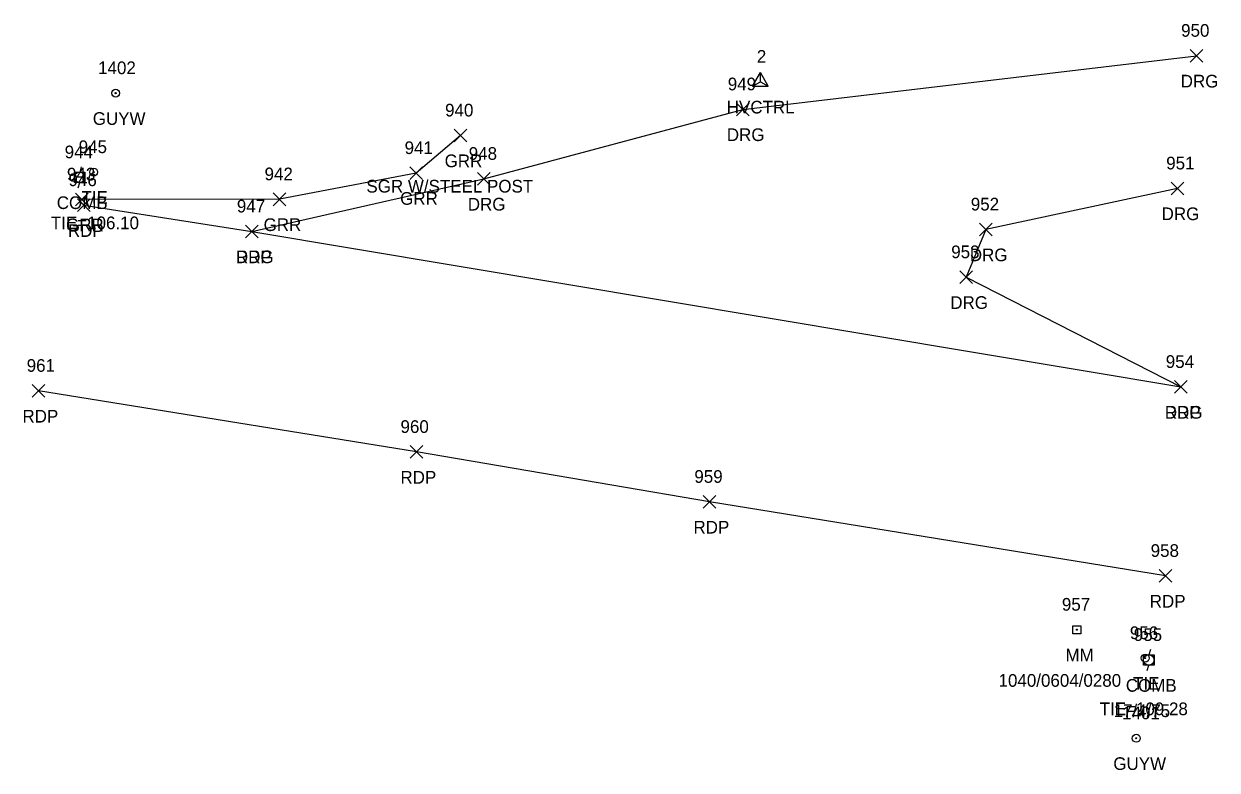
# Model space of a CAD drawing. Extents: x 1514253 to 1516033, y 782541 to 785002.
# Drawn here: x 1515845 to 1516033.2, y 782540.9 to 782658.6 of the extents above; entities that cross this region are included whole.
import ezdxf

# ---------------------------------------------------------------- set-up
doc = ezdxf.new("R2010")
doc.units = 0
for name, color, linetype in [('C_A', 7, 'Continuous'), ('C_C', 7, 'Continuous'), ('C_I', 7, 'Continuous'), ('CBP', 7, 'Continuous'), ('CPSM', 7, 'Continuous'), ('P_A', 7, 'Continuous'), ('P_I', 7, 'Continuous'), ('P_TIC', 7, 'Continuous'), ('PET', 7, 'Continuous'), ('R_A', 7, 'Continuous'), ('R_C', 7, 'Continuous'), ('R_I', 7, 'Continuous'), ('R_TIC', 7, 'Continuous'), ('RDG', 7, 'Continuous'), ('RGR', 7, 'Continuous'), ('S_A', 7, 'Continuous'), ('S_C', 7, 'Continuous'), ('S_I', 7, 'Continuous'), ('SRM', 7, 'Continuous'), ('U_A', 7, 'Continuous'), ('U_C', 7, 'Continuous'), ('U_I', 7, 'Continuous'), ('UP', 7, 'Continuous'), ('UPGW', 7, 'Continuous')]:
    doc.layers.add(name, color=color, linetype=linetype)

msp = doc.modelspace()

# ---------------------------------------------------------------- linework, layer by layer
at = {"layer": 'CBP'}
for centre, radius in [((1515856.01, 782635.23), 0.625), ((1515856.01, 782635.23), 0.0833), ((1516021.84, 782558.59), 0.625), ((1516021.84, 782558.59), 0.0833)]:
    msp.add_circle(centre, radius, dxfattribs=at)
at = {"layer": 'CPSM'}
for p, q in [((1515959.9, 782648.76), (1515961.15, 782650.92)), ((1515962.4, 782648.76), (1515961.15, 782650.92)), ((1515961.15, 782649.48), (1515961.15, 782650.92)), ((1515959.9, 782648.76), (1515961.15, 782649.48)), ((1515959.9, 782648.76), (1515962.4, 782648.76)), ((1515961.15, 782649.48), (1515961.15, 782649.48)), ((1515961.15, 782649.48), (1515962.4, 782648.76))]:
    msp.add_line(p, q, dxfattribs=at)
at = {"layer": 'P_TIC'}
for points in [[(1515853.46, 782629.02), (1515855.46, 782631.02)], [(1515855.46, 782629.02), (1515853.46, 782631.02)], [(1515879.96, 782624.87), (1515881.96, 782626.87)], [(1515881.96, 782624.87), (1515879.96, 782626.87)], [(1515846.3, 782599.74), (1515848.3, 782601.74)], [(1515848.3, 782599.74), (1515846.3, 782601.74)], [(1516026.44, 782600.35), (1516028.44, 782602.35)], [(1516028.44, 782600.35), (1516026.44, 782602.35)], [(1515905.9, 782590.1), (1515907.9, 782592.1)], [(1515907.9, 782590.1), (1515905.9, 782592.1)], [(1515952.11, 782582.23), (1515954.11, 782584.23)], [(1515954.11, 782582.23), (1515952.11, 782584.23)], [(1516024.06, 782570.55), (1516026.06, 782572.55)], [(1516026.06, 782570.55), (1516024.06, 782572.55)]]:
    msp.add_lwpolyline(points, dxfattribs=at)
at = {"layer": 'PET'}
for points in [[(1515854.46, 782630.02), (1515880.96, 782625.87), (1516027.44, 782601.35)], [(1516025.06, 782571.55), (1515953.11, 782583.23), (1515906.9, 782591.1), (1515847.3, 782600.74)]]:
    msp.add_lwpolyline(points, dxfattribs=at)
at = {"layer": 'R_TIC'}
for points in [[(1516028.95, 782652.58), (1516030.95, 782654.58)], [(1516030.95, 782652.58), (1516028.95, 782654.58)], [(1515957.38, 782644.13), (1515959.38, 782646.13)], [(1515959.38, 782644.13), (1515957.38, 782646.13)], [(1515912.88, 782640.01), (1515914.88, 782642.01)], [(1515914.88, 782640.01), (1515912.88, 782642.01)], [(1515905.85, 782634.08), (1515907.85, 782636.08)], [(1515907.85, 782634.08), (1515905.85, 782636.08)], [(1515916.52, 782633.17), (1515918.52, 782635.17)], [(1515918.52, 782633.17), (1515916.52, 782635.17)], [(1516025.94, 782631.66), (1516027.94, 782633.66)], [(1516027.94, 782631.66), (1516025.94, 782633.66)], [(1515853.16, 782629.91), (1515855.16, 782631.91)], [(1515855.16, 782629.91), (1515853.16, 782631.91)], [(1515884.33, 782629.94), (1515886.33, 782631.94)], [(1515886.33, 782629.94), (1515884.33, 782631.94)], [(1515879.96, 782624.87), (1515881.96, 782626.87)], [(1515881.96, 782624.87), (1515879.96, 782626.87)], [(1515995.69, 782625.18), (1515997.69, 782627.18)], [(1515997.69, 782625.18), (1515995.69, 782627.18)], [(1515992.61, 782617.66), (1515994.61, 782619.66)], [(1515994.61, 782617.66), (1515992.61, 782619.66)], [(1516026.44, 782600.35), (1516028.44, 782602.35)], [(1516028.44, 782600.35), (1516026.44, 782602.35)]]:
    msp.add_lwpolyline(points, dxfattribs=at)
at = {"layer": 'RDG'}
for points in [[(1515880.96, 782625.87), (1515917.52, 782634.17), (1515958.38, 782645.13), (1516029.95, 782653.58)], [(1516026.94, 782632.66), (1515996.69, 782626.18), (1515993.61, 782618.66), (1516027.44, 782601.35)]]:
    msp.add_lwpolyline(points, dxfattribs=at)
at = {"layer": 'RGR'}
msp.add_lwpolyline([(1515913.88, 782641.01), (1515906.85, 782635.08), (1515885.33, 782630.94), (1515854.16, 782630.91)], dxfattribs=at)
at = {"layer": 'SRM'}
msp.add_lwpolyline([(1516010.44, 782563.69), (1516011.69, 782563.69), (1516011.69, 782562.44), (1516010.44, 782562.44)], close=True, dxfattribs=at)
msp.add_circle((1516011.07, 782563.07), 0.0833, dxfattribs=at)
at = {"layer": 'UP'}
for p, q in [((1515852.97, 782633.58), (1515852.97, 782635.24)), ((1515852.97, 782635.24), (1515854.64, 782635.24)), ((1515854.06, 782636.08), (1515853.81, 782635.24)), ((1515854.64, 782635.24), (1515854.64, 782633.58)), ((1515854.64, 782633.58), (1515852.97, 782633.58)), ((1515853.56, 782632.74), (1515853.81, 782633.58)), ((1515853.81, 782634.41), (1515853.81, 782634.41)), ((1516022.65, 782559.96), (1516022.4, 782559.12)), ((1516021.56, 782557.46), (1516021.56, 782559.12)), ((1516021.56, 782559.12), (1516023.23, 782559.12)), ((1516022.4, 782558.29), (1516022.4, 782558.29)), ((1516023.23, 782559.12), (1516023.23, 782557.46)), ((1516023.23, 782557.46), (1516021.56, 782557.46)), ((1516022.15, 782556.62), (1516022.4, 782557.46))]:
    msp.add_line(p, q, dxfattribs=at)
for centre in [(1515853.81, 782634.41), (1516022.4, 782558.29)]:
    msp.add_circle(centre, 0.833, dxfattribs=at)
at = {"layer": 'UPGW'}
for centre, radius in [((1515859.48, 782647.68), 0.625), ((1515859.48, 782647.68), 0.0833), ((1516020.42, 782545.95), 0.625), ((1516020.42, 782545.95), 0.0833)]:
    msp.add_circle(centre, radius, dxfattribs=at)

# ---------------------------------------------------------------- texts
at = {"layer": 'C_A'}
for s, p in [('HVCTRL', (1515955.85, 782644.48)), ('TIE', (1515854.09, 782630.23)), ('TIE', (1516019.92, 782553.59))]:
    msp.add_text(s, height=2, dxfattribs=at).set_placement(p)
at = {"layer": 'C_C'}
for s, p in [('TIE=106.10', (1515849.26, 782626.23)), ('TIE=109.28', (1516014.66, 782549.59))]:
    msp.add_text(s, height=2, dxfattribs=at).set_placement(p)
at = {"layer": 'C_I'}
for s, p in [('2', (1515960.59, 782652.48)), ('945', (1515853.65, 782638.23)), ('956', (1516019.42, 782561.59))]:
    msp.add_text(s, height=2, dxfattribs=at).set_placement(p)
at = {"layer": 'P_A'}
for p in [(1515851.95, 782625.02), (1515878.44, 782620.87), (1515844.78, 782595.74), (1516024.93, 782596.35), (1515904.39, 782586.1), (1515950.6, 782578.23), (1516022.55, 782566.55)]:
    msp.add_text('RDP', height=2, dxfattribs=at).set_placement(p)
at = {"layer": 'P_I'}
for s, p in [('946', (1515852.04, 782633.02)), ('947', (1515878.59, 782628.87)), ('961', (1515845.45, 782603.74)), ('954', (1516025.08, 782604.35)), ('960', (1515904.4, 782594.1)), ('959', (1515950.74, 782586.23)), ('958', (1516022.7, 782574.55))]:
    msp.add_text(s, height=2, dxfattribs=at).set_placement(p)
at = {"layer": 'R_A'}
for s, p in [('DRG', (1516027.44, 782648.58)), ('DRG', (1515955.86, 782640.13)), ('GRR', (1515911.36, 782636.01)), ('GRR', (1515904.34, 782630.08)), ('DRG', (1515915.01, 782629.17)), ('DRG', (1516024.43, 782627.66)), ('GRR', (1515851.65, 782625.91)), ('GRR', (1515882.81, 782625.94)), ('DRG', (1515878.44, 782620.87)), ('DRG', (1515994.18, 782621.18)), ('DRG', (1515991.1, 782613.66)), ('DRG', (1516024.93, 782596.35))]:
    msp.add_text(s, height=2, dxfattribs=at).set_placement(p)
at = {"layer": 'R_C'}
msp.add_text('SGR W/STEEL POST', height=2, dxfattribs=at).set_placement((1515899.02, 782632.01))
at = {"layer": 'R_I'}
for s, p in [('950', (1516027.5, 782656.58)), ('949', (1515956.01, 782648.13)), ('940', (1515911.43, 782644.01)), ('941', (1515905.05, 782638.08)), ('948', (1515915.16, 782637.17)), ('951', (1516025.15, 782635.66)), ('943', (1515851.8, 782633.91)), ('942', (1515882.96, 782633.94)), ('952', (1515994.33, 782629.18)), ('947', (1515878.59, 782628.87)), ('953', (1515991.25, 782621.66)), ('954', (1516025.08, 782604.35))]:
    msp.add_text(s, height=2, dxfattribs=at).set_placement(p)
at = {"layer": 'S_A'}
msp.add_text('MM', height=2, dxfattribs=at).set_placement((1516009.26, 782558.07))
at = {"layer": 'S_C'}
msp.add_text('1040/0604/0280', height=2, dxfattribs=at).set_placement((1515998.71, 782554.07))
at = {"layer": 'S_I'}
msp.add_text('957', height=2, dxfattribs=at).set_placement((1516008.7, 782566.07))
at = {"layer": 'U_A'}
for s, p in [('GUYW', (1515855.87, 782642.68)), ('COMB', (1515850.19, 782629.41)), ('COMB', (1516018.78, 782553.29)), ('GUYW', (1516016.81, 782540.95))]:
    msp.add_text(s, height=2, dxfattribs=at).set_placement(p)
at = {"layer": 'U_C'}
msp.add_text('17/4/75', height=2, dxfattribs=at).set_placement((1516016.85, 782549.29))
at = {"layer": 'U_I'}
for s, p in [('1402', (1515856.71, 782650.68)), ('944', (1515851.44, 782637.41)), ('955', (1516020.04, 782561.29)), ('1401', (1516018.21, 782548.95))]:
    msp.add_text(s, height=2, dxfattribs=at).set_placement(p)

doc.saveas('drawing.dxf')
